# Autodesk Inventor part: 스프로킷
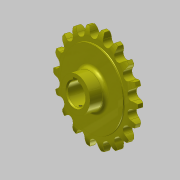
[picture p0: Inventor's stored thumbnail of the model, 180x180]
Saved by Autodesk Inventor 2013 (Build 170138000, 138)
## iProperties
Created: 2016-03
Part Number: 스프로킷
Material: 강철, 탄소
Document SubType Name: Modeling
Designer: mduedu
Density: 7.87 g/cm^3
Mass: 300.011 g
Surface Area: 127.848 cm^2
Volume: 38.1208 cm^3
Author: mduedu
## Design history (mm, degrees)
sketch "스케치1"
  geometry: L1 (0, 5)-(29.5, 5); L2 (29.5, 5)-(29.5, 4.1); L3 (30, 3.6)-(33.625, 3.6); L4 (40, 2)-(40, 0); L5 (40, 0)-(0, 0); L6 (0, 0)-(0, 5); L7 (0, -5)-(29.5, -5); L8 (29.5, -5)-(29.5, -4.1); L9 (30, -3.6)-(33.625, -3.6); L10 (40, -2)-(40, 0); L11 (0, 0)-(0, -5); A1 r 13.5 centre (33.625, -9.9) between (40, 2) and (33.625, 3.6); A2 r 13.5 centre (33.625, 9.9) between (33.625, -3.6) and (40, -2); A3 r 0.5 centre (30, 4.1) between (29.5, 4.1) and (30, 3.6); A4 r 0.5 centre (30, -4.1) between (30, -3.6) and (29.5, -4.1); 2 further points
  constraints: 22 end point, 8 point on circle, 6 symmetric about line, 5 tangent, 4 centre point, 4 parallel, 4 point on line, 1 equal radius, 1 horizontal, 1 perpendicular, 1 other
  dimensions: "d0" = 80 diameter of L4 L6; "d2" = 59 diameter of L2 L6; "d3" = 1.6 vertical distance of L4.start L3.end; "d4" = 3.6 distance from line of L4.end L3; "d5" = 5 distance between parallel lines of L5 L1; "d6" = 13.5 radius of A1; "d15" = 0.5 radius of A3
revolve "회전1" sketch "스케치1" stored, may be unused: angle "d7" = 90 deg
sketch "스케치2" dims "d8" = 65.2, "d11" = 80
  geometry: L1 (0, 0)-(0, 32.6); A1 r 36.57 centre (0, 0) between (-16.231, 32.771) and (0, 36.57); A2 r 3.97 centre (0, 36.57) between (-3.866, 35.665) and (0, 32.6); A3 r 12.7 centre (-16.231, 32.771) between (-3.866, 35.665) and (-5.534, 39.615); A4 r 12.7 centre (16.231, 32.771) between (5.534, 39.615) and (3.866, 35.665); A5 r 3.97 centre (0, 36.57) between (0, 32.6) and (3.866, 35.665); A6 r 40 centre (0, 0) between (5.534, 39.615) and (-5.534, 39.615); 2 further points
  constraints: 12 point on circle, 6 centre point, 4 coincident, 3 symmetric about line, 2 end point, 1 point on line, 1 tangent, 1 vertical, 1 vertical alignment, 7 other
  dimensions: "d10" = 73.14 diameter of A1; "d12" = 12.7 radius of A3
extrude "돌출1" cut sketch "스케치2" stored distance "d13" = 10; taper "d14" = 0 deg
sketch "스케치3"
  geometry: C1 r 13.5 at (0, 0); 1 further point
  constraints: 1 centre point, 1 coincident
  dimensions: "d19" = 27 diameter of C1
extrude "돌출2" join sketch "스케치3" distance "d20" = 13; taper "d21" = 0 deg
fillet "모깎기1" dims "d22" = 3
sketch "스케치4"
  geometry: L1 (-2.5, 0)-(2.5, 0); L2 (2.5, 0)-(2.5, 10.8); L3 (2.5, 10.8)-(-2.5, 10.8); L4 (-2.5, 10.8)-(-2.5, 0); C1 r 8.5 at (0, 0); 2 further points
  constraints: 8 end point, 2 coincident, 2 parallel, 1 centre point, 1 horizontal, 1 midpoint, 1 perpendicular
  dimensions: "d23" = 17 diameter of C1; "d25" = 5 distance of L2.end L3.end; "d26" = 10.8 distance of L1.end L2.end
extrude "돌출3" cut sketch "스케치4" stored distance "d27" = 8; taper "d28" = 0 deg
chamfer "모따기1" distance "d29" = 1; stored, may be unused: second distance "d30" = 2, angle "d31" = 45 deg
node "작업 평면1"
sketch "스케치5"
  geometry: L1 (13.5, 13)-(-13.5, 13) reference; 2 further points
  constraints: 1 vertical alignment
  dimensions: "d32" = 4 distance from line of point (0, 9) L1
hole "구멍1" sketch "스케치5" at (0, 9) diameter "d33" = 2.459; stored, may be unused: countersink angle "d37" = 90 deg, drill point angle "d39" = 118 deg; dims "d34" = 6, "d35" = 4, "d36" = 2, "d38" = 8
node "솔리드1"
pattern_circular "원형 패턴1" dims angle "d17" = 360 deg
